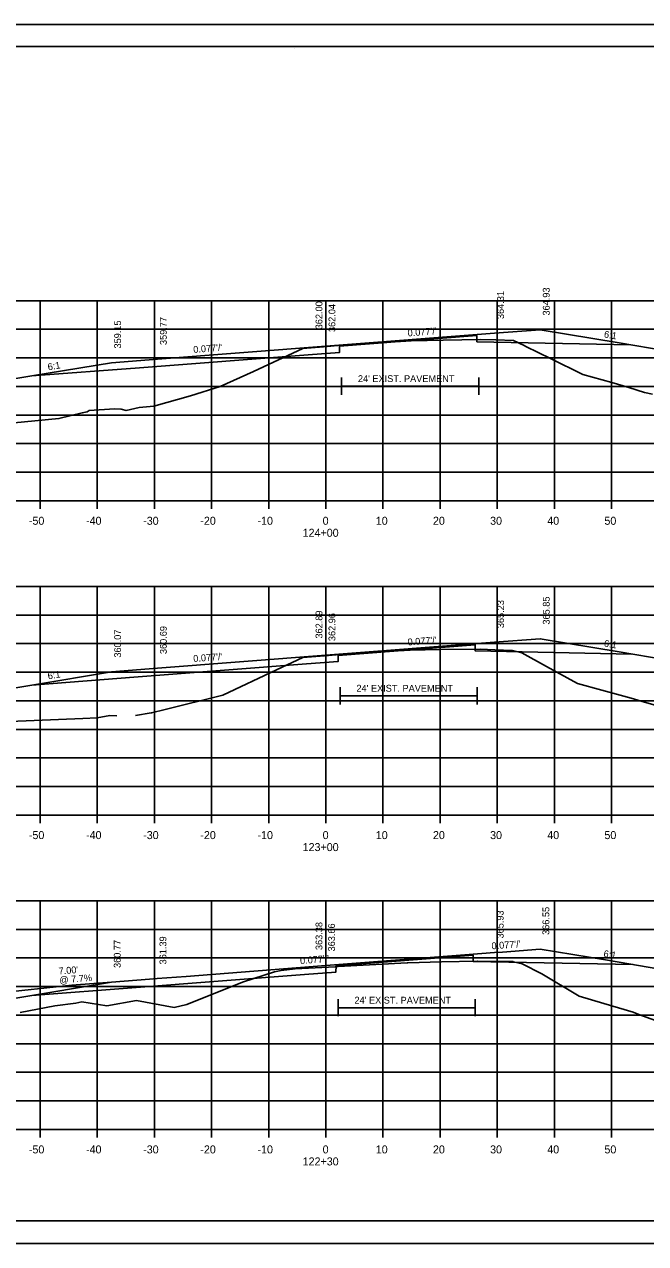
# Model space of a CAD drawing. Extents: x 1374859 to 1376773, y 382242 to 389804.
# Drawn here: x 1376081.8 to 1376190.5, y 384375.1 to 384588.5 of the extents above; entities that cross this region are included whole.
import ezdxf

# ---------------------------------------------------------------- set-up
doc = ezdxf.new("R2010")
doc.units = 0
for name, color, linetype in [('R_Axis', 7, 'Continuous'), ('R_Axis Annot', 7, 'Continuous'), ('R_Border', 7, 'Continuous'), ('R_Border Notes', 7, 'Continuous'), ('R_Drive', 7, 'Continuous'), ('R_Exist Surface', 7, 'Continuous'), ('R_Fin Surface', 7, 'Continuous'), ('R_Grid', 7, 'Continuous'), ('R_No Plot', 7, 'Continuous'), ('R_Xsect Elev', 7, 'Continuous'), ('R_Xsect Slope', 7, 'Continuous')]:
    doc.layers.add(name, color=color, linetype=linetype)

msp = doc.modelspace()

# ---------------------------------------------------------------- linework, layer by layer
at = {"layer": 'R_Axis'}
for p, q in [((1375994.57, 384505.1), (1376274.57, 384505.1)), ((1376084.57, 384503.7), (1376084.57, 384505.1)), ((1376094.57, 384503.7), (1376094.57, 384505.1)), ((1376104.57, 384503.7), (1376104.57, 384505.1)), ((1376114.57, 384503.7), (1376114.57, 384505.1)), ((1376124.57, 384503.7), (1376124.57, 384505.1)), ((1376134.57, 384503.7), (1376134.57, 384505.1)), ((1376144.57, 384503.7), (1376144.57, 384505.1)), ((1376154.57, 384503.7), (1376154.57, 384505.1)), ((1376164.57, 384503.7), (1376164.57, 384505.1)), ((1376174.57, 384503.7), (1376174.57, 384505.1)), ((1376184.57, 384503.7), (1376184.57, 384505.1)), ((1375994.57, 384450.1), (1376274.57, 384450.1)), ((1376084.57, 384448.7), (1376084.57, 384450.1)), ((1376094.57, 384448.7), (1376094.57, 384450.1)), ((1376104.57, 384448.7), (1376104.57, 384450.1)), ((1376114.57, 384448.7), (1376114.57, 384450.1)), ((1376124.57, 384448.7), (1376124.57, 384450.1)), ((1376134.57, 384448.7), (1376134.57, 384450.1)), ((1376144.57, 384448.7), (1376144.57, 384450.1)), ((1376154.57, 384448.7), (1376154.57, 384450.1)), ((1376164.57, 384448.7), (1376164.57, 384450.1)), ((1376174.57, 384448.7), (1376174.57, 384450.1)), ((1376184.57, 384448.7), (1376184.57, 384450.1)), ((1375994.57, 384395.1), (1376274.57, 384395.1)), ((1376084.57, 384393.7), (1376084.57, 384395.1)), ((1376094.57, 384393.7), (1376094.57, 384395.1)), ((1376104.57, 384393.7), (1376104.57, 384395.1)), ((1376114.57, 384393.7), (1376114.57, 384395.1)), ((1376124.57, 384393.7), (1376124.57, 384395.1)), ((1376134.57, 384393.7), (1376134.57, 384395.1)), ((1376144.57, 384393.7), (1376144.57, 384395.1)), ((1376154.57, 384393.7), (1376154.57, 384395.1)), ((1376164.57, 384393.7), (1376164.57, 384395.1)), ((1376174.57, 384393.7), (1376174.57, 384395.1)), ((1376184.57, 384393.7), (1376184.57, 384395.1))]:
    msp.add_line(p, q, dxfattribs=at)
at = {"layer": 'R_Border'}
for p, q in [((1375976.57, 384584.56), (1376292.75, 384584.56)), ((1376129.09, 384584.3), (1376129.09, 384584.3)), ((1376129.09, 384584.3), (1376129.09, 384584.3)), ((1376292.75, 384379.1), (1375976.57, 384379.1))]:
    msp.add_line(p, q, dxfattribs=at)
at = {"layer": 'R_Border Notes'}
for points in [[(1376137.31, 384526.65), (1376137.31, 384523.65)], [(1376161.31, 384526.65), (1376161.31, 384523.65)], [(1376137.31, 384525.15), (1376161.31, 384525.15)], [(1376137.05, 384472.47), (1376137.05, 384469.47)], [(1376137.05, 384470.97), (1376161.05, 384470.97)], [(1376161.05, 384472.47), (1376161.05, 384469.47)], [(1376136.71, 384417.89), (1376136.71, 384414.89)], [(1376160.71, 384417.89), (1376160.71, 384414.89)], [(1376136.71, 384416.39), (1376160.71, 384416.39)]]:
    msp.add_lwpolyline(points, dxfattribs=at)
at = {"layer": 'R_Drive'}
for p, q in [((1376012.81, 384411.93), (1376090.1, 384420.34)), ((1376090.1, 384420.34), (1376097.08, 384420.87))]:
    msp.add_line(p, q, dxfattribs=at)
at = {"layer": 'R_Exist Surface'}
for points in [[(1376077.65, 384518.51), (1376087.88, 384519.49), (1376091.95, 384520.46), (1376092.82, 384520.67), (1376093.14, 384520.89), (1376097.6, 384521.2), (1376098.75, 384521.13), (1376099.63, 384520.92), (1376101.91, 384521.42), (1376104.5, 384521.65), (1376110.87, 384523.48), (1376116.09, 384525.12), (1376121.92, 384527.73), (1376130.57, 384531.73), (1376134.18, 384532.06), (1376137.31, 384532.35), (1376143.92, 384532.76), (1376149.48, 384533.08), (1376155.11, 384533.19), (1376161.63, 384533.32), (1376164.33, 384533.25), (1376167.41, 384533.14), (1376169.27, 384532.24), (1376169.59, 384532.08), (1376173.88, 384529.97), (1376179.52, 384527.17), (1376184.62, 384525.8), (1376187.59, 384524.91), (1376190.31, 384524.07), (1376191.75, 384523.77)], [(1376101.26, 384467.53), (1376104.02, 384467.98), (1376104.09, 384467.97), (1376106.46, 384468.58), (1376116.55, 384471.09), (1376125.96, 384475.53), (1376130.53, 384477.69), (1376134.31, 384477.98), (1376137.05, 384478.18), (1376144.03, 384478.64), (1376149.32, 384478.98), (1376154.63, 384479.06), (1376161.59, 384479.16), (1376164.13, 384479.04), (1376167.2, 384478.9), (1376168.15, 384478.69), (1376168.88, 384478.51), (1376173.15, 384476.12), (1376178.61, 384473.12), (1376182.87, 384471.98), (1376188, 384470.57), (1376190.33, 384469.88), (1376192.22, 384469.36)], [(1375994.57, 384464.47), (1376009.64, 384464.65), (1376017.53, 384464.78), (1376019.08, 384464.81), (1376047.24, 384465.51), (1376058.31, 384465.81), (1376074.95, 384466.32), (1376092.04, 384467.02), (1376094.54, 384467.14), (1376096.78, 384467.5), (1376097.99, 384467.49)], [(1376081.11, 384415.55), (1376087.18, 384416.72), (1376090.81, 384417.21), (1376091.9, 384417.41), (1376096.27, 384416.73), (1376101.45, 384417.65), (1376108.06, 384416.44), (1376110.23, 384416.93), (1376119.96, 384420.89), (1376125.56, 384422.66), (1376126.77, 384422.88), (1376129.18, 384423.2), (1376136.19, 384423.56), (1376136.32, 384423.57), (1376136.71, 384423.59), (1376148.77, 384424.25), (1376148.9, 384424.25), (1376154.82, 384424.4), (1376161.04, 384424.56), (1376161.1, 384424.56), (1376167.33, 384424.46), (1376167.38, 384424.44), (1376168.91, 384424.06), (1376172.35, 384422.3), (1376178.89, 384418.41), (1376183.21, 384417.13), (1376188.33, 384415.62), (1376189.36, 384415.18), (1376195, 384413.18)]]:
    msp.add_lwpolyline(points, dxfattribs=at)
at = {"layer": 'R_Fin Surface'}
for points in [[(1376049.43, 384518.16), (1376051.13, 384517.6), (1376075.09, 384525.59), (1376083.13, 384526.93), (1376097.09, 384529.25), (1376105.09, 384529.87), (1376134.59, 384532.14), (1376164.09, 384534.41), (1376172.09, 384535.03), (1376185.9, 384532.73), (1376194.09, 384531.36), (1376225.13, 384521.01)], [(1376083.13, 384526.93), (1376101.99, 384528.38), (1376131.47, 384530.65), (1376136.97, 384531.07), (1376136.98, 384532.15), (1376160.98, 384534.01), (1376160.99, 384532.92), (1376187.95, 384532.38)], [(1376046.15, 384465.48), (1376051.59, 384463.67), (1376075.09, 384471.5), (1376083.13, 384472.85), (1376097.09, 384475.17), (1376105.09, 384475.79), (1376134.59, 384478.06), (1376164.09, 384480.33), (1376172.09, 384480.95), (1376185.9, 384478.64), (1376194.09, 384477.28), (1376228.04, 384465.96)], [(1376083.13, 384472.85), (1376101.72, 384474.28), (1376131.2, 384476.55), (1376136.7, 384476.97), (1376136.71, 384478.05), (1376160.71, 384479.9), (1376160.72, 384478.82), (1376188.13, 384478.27)], [(1376064.09, 384413.54), (1376073.29, 384416.61), (1376075.08, 384417.21), (1376081.72, 384418.31), (1376083.13, 384418.55), (1376094.64, 384420.47), (1376097.08, 384420.87), (1376103.69, 384421.38), (1376105.08, 384421.49), (1376110.14, 384421.88), (1376134.58, 384423.76), (1376158.89, 384425.63), (1376164.08, 384426.03), (1376165.47, 384426.14), (1376172.08, 384426.65), (1376183.48, 384424.75), (1376185.9, 384424.35), (1376192.66, 384423.22), (1376194.08, 384422.98), (1376200.51, 384420.84), (1376231.7, 384410.44)], [(1376083.13, 384418.55), (1376101.36, 384419.95), (1376130.84, 384422.22), (1376136.34, 384422.64), (1376136.35, 384423.73), (1376160.35, 384425.58), (1376160.36, 384424.49), (1376188.36, 384423.93)]]:
    msp.add_lwpolyline(points, dxfattribs=at)
at = {"layer": 'R_Grid'}
for p, q in [((1375994.57, 384540.1), (1376274.57, 384540.1)), ((1376084.57, 384505.1), (1376084.57, 384540.1)), ((1376094.57, 384505.1), (1376094.57, 384540.1)), ((1376104.57, 384505.1), (1376104.57, 384540.1)), ((1376114.57, 384505.1), (1376114.57, 384540.1)), ((1376124.57, 384505.1), (1376124.57, 384540.1)), ((1376134.57, 384505.1), (1376134.57, 384540.1)), ((1376144.57, 384505.1), (1376144.57, 384540.1)), ((1376154.57, 384505.1), (1376154.57, 384540.1)), ((1376164.57, 384505.1), (1376164.57, 384540.1)), ((1376174.57, 384505.1), (1376174.57, 384540.1)), ((1376184.57, 384505.1), (1376184.57, 384540.1)), ((1375994.57, 384535.1), (1376274.57, 384535.1)), ((1375994.57, 384530.1), (1376274.57, 384530.1)), ((1375994.57, 384525.1), (1376274.57, 384525.1)), ((1375994.57, 384520.1), (1376274.57, 384520.1)), ((1375994.57, 384515.1), (1376274.57, 384515.1)), ((1375994.57, 384510.1), (1376274.57, 384510.1)), ((1375994.57, 384505.1), (1376274.57, 384505.1)), ((1375994.57, 384490.1), (1376274.57, 384490.1)), ((1376084.57, 384450.1), (1376084.57, 384490.1)), ((1376094.57, 384450.1), (1376094.57, 384490.1)), ((1376104.57, 384450.1), (1376104.57, 384490.1)), ((1376114.57, 384450.1), (1376114.57, 384490.1)), ((1376124.57, 384450.1), (1376124.57, 384490.1)), ((1376134.57, 384450.1), (1376134.57, 384490.1)), ((1376144.57, 384450.1), (1376144.57, 384490.1)), ((1376154.57, 384450.1), (1376154.57, 384490.1)), ((1376164.57, 384450.1), (1376164.57, 384490.1)), ((1376174.57, 384450.1), (1376174.57, 384490.1)), ((1376184.57, 384450.1), (1376184.57, 384490.1)), ((1375994.57, 384485.1), (1376274.57, 384485.1)), ((1375994.57, 384480.1), (1376274.57, 384480.1)), ((1375994.57, 384475.1), (1376274.57, 384475.1)), ((1375994.57, 384470.1), (1376274.57, 384470.1)), ((1375994.57, 384465.1), (1376274.57, 384465.1)), ((1375994.57, 384460.1), (1376274.57, 384460.1)), ((1375994.57, 384455.1), (1376274.57, 384455.1)), ((1375994.57, 384450.1), (1376274.57, 384450.1)), ((1375994.57, 384435.1), (1376274.57, 384435.1)), ((1376084.57, 384395.1), (1376084.57, 384435.1)), ((1376094.57, 384395.1), (1376094.57, 384435.1)), ((1376104.57, 384395.1), (1376104.57, 384435.1)), ((1376114.57, 384395.1), (1376114.57, 384435.1)), ((1376124.57, 384395.1), (1376124.57, 384435.1)), ((1376134.57, 384395.1), (1376134.57, 384435.1)), ((1376144.57, 384395.1), (1376144.57, 384435.1)), ((1376154.57, 384395.1), (1376154.57, 384435.1)), ((1376164.57, 384395.1), (1376164.57, 384435.1)), ((1376174.57, 384395.1), (1376174.57, 384435.1)), ((1376184.57, 384395.1), (1376184.57, 384435.1)), ((1375994.57, 384430.1), (1376274.57, 384430.1)), ((1375994.57, 384425.1), (1376274.57, 384425.1)), ((1375994.57, 384420.1), (1376274.57, 384420.1)), ((1375994.57, 384415.1), (1376274.57, 384415.1)), ((1375994.57, 384410.1), (1376274.57, 384410.1)), ((1375994.57, 384405.1), (1376274.57, 384405.1)), ((1375994.57, 384400.1), (1376274.57, 384400.1)), ((1375994.57, 384395.1), (1376274.57, 384395.1))]:
    msp.add_line(p, q, dxfattribs=at)
at = {"layer": 'R_No Plot'}
for p, q in [((1375964.17, 384588.45), (1376297.5, 384588.45)), ((1375964.17, 384375.12), (1376297.5, 384375.12))]:
    msp.add_line(p, q, dxfattribs=at)
for points in [[(1375964.16, 384588.45), (1376297.5, 384588.45), (1376297.5, 384375.12), (1375964.16, 384375.12)], [(1376210.49, 384584.56), (1376210.49, 384574.68), (1376246.22, 384574.68), (1376246.22, 384571.76), (1376269.42, 384571.76), (1376269.42, 384547.43), (1376292.75, 384547.43), (1376292.75, 384379.1), (1375976.57, 384379.1), (1375976.57, 384584.56)]]:
    msp.add_lwpolyline(points, close=True, dxfattribs=at)

# ---------------------------------------------------------------- texts
at = {"layer": 'R_Axis Annot'}
for s, p in [('-50', (1376082.61, 384500.9)), ('-40', (1376092.61, 384500.9)), ('-30', (1376102.61, 384500.9)), ('-20', (1376112.61, 384500.9)), ('-10', (1376122.61, 384500.9)), ('0', (1376134.01, 384500.9)), ('10', (1376143.31, 384500.9)), ('20', (1376153.31, 384500.9)), ('30', (1376163.31, 384500.9)), ('40', (1376173.31, 384500.9)), ('50', (1376183.31, 384500.9)), ('124+00', (1376130.51, 384498.8)), ('-50', (1376082.61, 384445.9)), ('-40', (1376092.61, 384445.9)), ('-30', (1376102.61, 384445.9)), ('-20', (1376112.61, 384445.9)), ('-10', (1376122.61, 384445.9)), ('0', (1376134.01, 384445.9)), ('10', (1376143.31, 384445.9)), ('20', (1376153.31, 384445.9)), ('30', (1376163.31, 384445.9)), ('40', (1376173.31, 384445.9)), ('50', (1376183.31, 384445.9)), ('123+00', (1376130.51, 384443.8)), ('-50', (1376082.61, 384390.9)), ('-40', (1376092.61, 384390.9)), ('-30', (1376102.61, 384390.9)), ('-20', (1376112.61, 384390.9)), ('-10', (1376122.61, 384390.9)), ('0', (1376134.01, 384390.9)), ('10', (1376143.31, 384390.9)), ('20', (1376153.31, 384390.9)), ('30', (1376163.31, 384390.9)), ('40', (1376173.31, 384390.9)), ('50', (1376183.31, 384390.9)), ('122+30', (1376130.51, 384388.8))]:
    msp.add_text(s, height=1.4, dxfattribs=at).set_placement(p)
at = {"layer": 'R_Border Notes'}
for p in [(1376140.18, 384525.87), (1376139.92, 384471.69), (1376139.58, 384417.11)]:
    msp.add_text("24' EXIST. PAVEMENT", height=1.2, rotation=0, dxfattribs=at).set_placement(p)
at = {"layer": 'R_Xsect Elev'}
for s, p in [('364.31', (1376165.74, 384536.89)), ('364.93', (1376173.74, 384537.51)), ('362.00', (1376133.97, 384535.1)), ('362.04', (1376136.24, 384534.62)), ('359.77', (1376106.74, 384532.35)), ('359.15', (1376098.74, 384531.74)), ('365.85', (1376173.74, 384483.43)), ('362.89', (1376133.97, 384480.99)), ('365.23', (1376165.74, 384482.81)), ('362.96', (1376136.24, 384480.54)), ('360.07', (1376098.74, 384477.65)), ('360.69', (1376106.74, 384478.27)), ('365.93', (1376165.67, 384428.51)), ('366.55', (1376173.67, 384429.13)), ('363.38', (1376133.97, 384426.48)), ('363.66', (1376136.17, 384426.24)), ('360.77', (1376098.67, 384423.35)), ('361.39', (1376106.67, 384423.97))]:
    msp.add_text(s, height=1.2, rotation=90, dxfattribs=at).set_placement(p)
at = {"layer": 'R_Xsect Slope'}
for s, rotation, p in [("0.077'/'", 4.4031, (1376148.92, 384533.85)), ('6:1', 350.5358, (1376183.17, 384533.69)), ("0.077'/'", 4.4031, (1376111.42, 384530.96)), ('6:1', 9.4642, (1376086, 384527.91)), ("0.077'/'", 4.4031, (1376148.92, 384479.77)), ('6:1', 350.5358, (1376183.17, 384479.61)), ("0.077'/'", 4.4031, (1376111.42, 384476.88)), ('6:1', 9.4642, (1376086, 384473.83)), ("0.077'/'", 4.4033, (1376163.6, 384426.6)), ('6:1', 350.5355, (1376183.09, 384425.31)), ("0.077'/'", 4.4033, (1376130.1, 384424.02)), ("7.00'", 4.586, (1376087.86, 384422.2)), ('@ 7.7%', 4.586, (1376087.98, 384420.62))]:
    msp.add_text(s, height=1.2, rotation=rotation, dxfattribs=at).set_placement(p)

doc.saveas('drawing.dxf')
